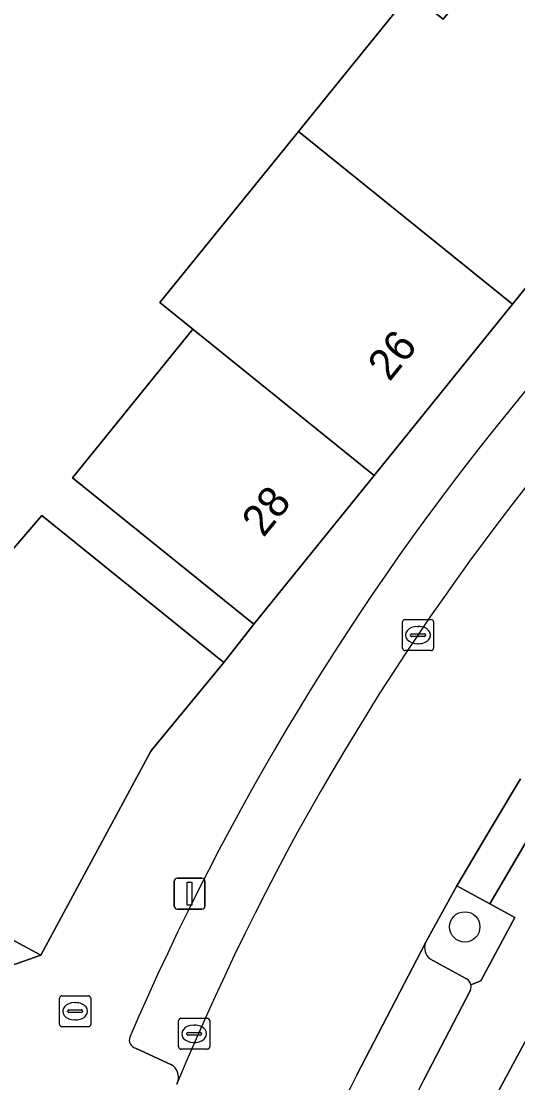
# Model space of a CAD drawing. Extents: x 159716 to 160783, y 383290 to 384031.
# Drawn here: x 160307.9 to 160323.91, y 383399.58 to 383433.83 of the extents above; entities that cross this region are included whole.
import ezdxf

# ---------------------------------------------------------------- set-up
doc = ezdxf.new("R2010")
doc.units = 0
for name, color, linetype in [('IMGEO_Boom', 7, 'Continuous'), ('IMGEO_Brandkraan', 7, 'Continuous'), ('IMGEO_Erf', 7, 'Continuous'), ('IMGEO_Groenvoorziening', 7, 'Continuous'), ('IMGEO_Kolk', 7, 'Continuous'), ('IMGEO_Lichtmast', 7, 'Continuous'), ('IMGEO_Pand', 7, 'Continuous'), ('IMGEO_Pand_nummerreeks', 7, 'Continuous'), ('IMGEO_Parkeervlak_open', 7, 'Continuous'), ('IMGEO_Rijbaan_lokaal_open', 7, 'Continuous'), ('IMGEO_Voetpad_open', 7, 'Continuous')]:
    doc.layers.add(name, color=color, linetype=linetype)

msp = doc.modelspace()

# ---------------------------------------------------------------- linework, layer by layer
at = {"layer": 'IMGEO_Boom'}
msp.add_circle((160322.206, 383404.609), 0.489, dxfattribs=at)
at = {"layer": 'IMGEO_Brandkraan'}
for p, q in [((160309.139, 383401.46), (160309.139, 383402.312)), ((160309.214, 383402.386), (160310.066, 383402.386)), ((160310.14, 383402.312), (160310.14, 383401.46)), ((160309.441, 383401.929), (160309.839, 383401.929)), ((160309.627, 383402.166), (160309.652, 383402.166)), ((160309.398, 383401.88), (160309.398, 383401.892)), ((160309.836, 383401.843), (160309.438, 383401.843)), ((160309.65, 383401.606), (160309.625, 383401.606)), ((160309.882, 383401.892), (160309.882, 383401.88)), ((160310.066, 383401.386), (160309.214, 383401.386))]:
    msp.add_line(p, q, dxfattribs=at)
for points in [[(160309.139, 383401.46), (160309.139, 383402.312)], [(160309.214, 383402.386), (160310.066, 383402.386)], [(160310.14, 383402.312), (160310.14, 383401.46)], [(160310.066, 383401.386), (160309.214, 383401.386)]]:
    msp.add_lwpolyline(points, dxfattribs=at)
for centre, radius, start, end in [((160309.216, 383402.31), 0.0765, 91.552, 178.448), ((160309.216, 383402.31), 0.0765, 91.552, 178.448), ((160310.064, 383402.31), 0.0765, 1.552, 88.448), ((160310.064, 383402.31), 0.0765, 1.552, 88.448), ((160309.438, 383401.889), 0.0403, 85.8775, 175.7526), ((160309.843, 383401.891), 0.0386, 1.7309, 96.639), ((160309.435, 383401.879), 0.0366, 178.938, 274.7102), ((160309.839, 383401.886), 0.043, 264.8664, 352.4533), ((160309.216, 383401.462), 0.0765, 181.552, 268.448), ((160309.216, 383401.462), 0.0765, 181.552, 268.448), ((160310.064, 383401.462), 0.0765, 271.552, 358.448), ((160310.064, 383401.462), 0.0765, 271.552, 358.448)]:
    msp.add_arc(centre, radius, start, end, dxfattribs=at)
for centre, major_axis, ratio, start_param, end_param in [((160309.626, 383401.886), (-0.387, 0.002), 0.722429, 4.712389, 7.853982), ((160309.651, 383401.886), (-0.39, 0.002), 0.717154, 1.570796, 4.712389)]:
    msp.add_ellipse(centre, major_axis=major_axis, ratio=ratio, start_param=start_param, end_param=end_param, dxfattribs=at)
at = {"layer": 'IMGEO_Erf'}
msp.add_lwpolyline([(160305.278, 383414.052), (160308.565, 383417.879), (160314.432, 383413.138), (160315.404, 383414.378), (160309.554, 383419.103), (160313.43, 383423.901), (160312.375, 383424.754), (160316.84, 383430.281), (160320.453, 383434.753), (160321.507, 383433.901), (160326.319, 383439.857), (160327.363, 383439.013), (160330.852, 383443.362), (160330.036, 383444.593), (160325.09, 383452.053), (160320.906, 383458.365), (160327.156, 383462.508)], dxfattribs=at)
at = {"layer": 'IMGEO_Groenvoorziening'}
for points in [[(160323.018, 383405.349), (160321.949, 383405.931), (160320.969, 383404.161), (160320.94, 383404.099)], [(160322.402, 383402.741), (160322.724, 383402.864), (160323.82, 383404.913), (160323.018, 383405.349)], [(160321.083, 383403.578), (160322.258, 383402.931)]]:
    msp.add_lwpolyline(points, dxfattribs=at)
for centre, radius, start, end in [((160321.364, 383403.935), 0.454, 158.8551, 231.8411), ((160322.127, 383402.682), 0.282, 12.1167, 62.1999)]:
    msp.add_arc(centre, radius, start, end, dxfattribs=at)
at = {"layer": 'IMGEO_Kolk'}
for p, q in [((160320.196, 383413.6), (160320.196, 383414.452)), ((160320.271, 383414.526), (160321.123, 383414.526)), ((160320.684, 383414.306), (160320.709, 383414.306)), ((160321.197, 383414.452), (160321.197, 383413.6)), ((160320.455, 383414.02), (160320.455, 383414.032)), ((160320.893, 383413.983), (160320.495, 383413.983)), ((160320.498, 383414.069), (160320.896, 383414.069)), ((160320.939, 383414.032), (160320.939, 383414.02)), ((160320.707, 383413.746), (160320.682, 383413.746)), ((160321.123, 383413.526), (160320.271, 383413.526)), ((160312.977, 383400.734), (160312.977, 383401.586)), ((160313.052, 383401.66), (160313.904, 383401.66)), ((160313.978, 383401.586), (160313.978, 383400.734)), ((160313.465, 383401.44), (160313.49, 383401.44)), ((160313.236, 383401.154), (160313.236, 383401.166)), ((160313.674, 383401.117), (160313.276, 383401.117)), ((160313.279, 383401.203), (160313.677, 383401.203)), ((160313.72, 383401.166), (160313.72, 383401.154)), ((160313.904, 383400.66), (160313.052, 383400.66)), ((160313.488, 383400.88), (160313.463, 383400.88))]:
    msp.add_line(p, q, dxfattribs=at)
for points in [[(160320.196, 383413.6), (160320.196, 383414.452)], [(160320.271, 383414.526), (160321.123, 383414.526)], [(160321.197, 383414.452), (160321.197, 383413.6)], [(160321.123, 383413.526), (160320.271, 383413.526)], [(160312.977, 383400.734), (160312.977, 383401.586)], [(160313.052, 383401.66), (160313.904, 383401.66)], [(160313.978, 383401.586), (160313.978, 383400.734)], [(160313.904, 383400.66), (160313.052, 383400.66)]]:
    msp.add_lwpolyline(points, dxfattribs=at)
for centre, radius, start, end in [((160320.273, 383414.45), 0.0765, 91.552, 178.448), ((160320.273, 383414.45), 0.0765, 91.552, 178.448), ((160321.121, 383414.45), 0.0765, 1.552, 88.448), ((160321.121, 383414.45), 0.0765, 1.552, 88.448), ((160320.495, 383414.029), 0.0403, 85.8775, 175.7526), ((160320.492, 383414.019), 0.0366, 178.938, 274.7102), ((160320.896, 383414.026), 0.043, 264.8664, 352.4533), ((160320.9, 383414.031), 0.0386, 1.7309, 96.639), ((160320.273, 383413.602), 0.0765, 181.552, 268.448), ((160320.273, 383413.602), 0.0765, 181.552, 268.448), ((160321.121, 383413.602), 0.0765, 271.552, 358.448), ((160321.121, 383413.602), 0.0765, 271.552, 358.448), ((160313.054, 383401.584), 0.0765, 91.552, 178.448), ((160313.054, 383401.584), 0.0765, 91.552, 178.448), ((160313.902, 383401.584), 0.0765, 1.552, 88.448), ((160313.902, 383401.584), 0.0765, 1.552, 88.448), ((160313.276, 383401.163), 0.0403, 85.8775, 175.7526), ((160313.273, 383401.153), 0.0366, 178.938, 274.7102), ((160313.677, 383401.16), 0.043, 264.8664, 352.4533), ((160313.681, 383401.165), 0.0386, 1.7309, 96.639), ((160313.054, 383400.736), 0.0765, 181.552, 268.448), ((160313.054, 383400.736), 0.0765, 181.552, 268.448), ((160313.902, 383400.736), 0.0765, 271.552, 358.448), ((160313.902, 383400.736), 0.0765, 271.552, 358.448)]:
    msp.add_arc(centre, radius, start, end, dxfattribs=at)
for centre, major_axis, ratio, start_param, end_param in [((160320.683, 383414.026), (-0.387, 0.002), 0.722429, 4.712389, 7.853982), ((160320.708, 383414.026), (-0.39, 0.002), 0.717154, 1.570796, 4.712389), ((160313.464, 383401.16), (-0.387, 0.002), 0.722429, 4.712389, 7.853982), ((160313.489, 383401.16), (-0.39, 0.002), 0.717154, 1.570796, 4.712389)]:
    msp.add_ellipse(centre, major_axis=major_axis, ratio=ratio, start_param=start_param, end_param=end_param, dxfattribs=at)
at = {"layer": 'IMGEO_Lichtmast'}
for p, q in [((160312.835, 383405.281), (160312.835, 383406.081)), ((160312.835, 383406.081), (160312.835, 383405.281)), ((160312.935, 383406.181), (160313.725, 383406.181)), ((160313.725, 383406.181), (160312.935, 383406.181)), ((160313.825, 383406.081), (160313.825, 383405.281)), ((160313.825, 383405.281), (160313.825, 383406.081)), ((160313.725, 383405.181), (160312.935, 383405.181)), ((160312.935, 383405.181), (160313.725, 383405.181))]:
    msp.add_line(p, q, dxfattribs=at)
msp.add_lwpolyline([(160313.255, 383406.056), (160313.405, 383406.056), (160313.405, 383405.306), (160313.255, 383405.306), (160313.255, 383406.056)], dxfattribs=at)
for centre, start, end in [((160312.935, 383406.081), 90, 180), ((160312.935, 383406.081), 90, 180), ((160313.725, 383406.081), 0, 90), ((160313.725, 383406.081), 360, 90), ((160312.935, 383405.281), 180, 270), ((160312.935, 383405.281), 180, 270), ((160313.725, 383405.281), 270, 0), ((160313.725, 383405.281), 270, 0)]:
    msp.add_arc(centre, 0.1, start, end, dxfattribs=at)
at = {"layer": 'IMGEO_Pand'}
for points in [[(160327.363, 383439.013), (160326.319, 383439.857), (160321.507, 383433.901), (160320.453, 383434.753), (160316.84, 383430.281), (160323.745, 383424.702), (160327.357, 383429.173), (160332.168, 383435.128)], [(160316.84, 383430.281), (160312.375, 383424.754), (160313.43, 383423.901), (160319.278, 383419.173), (160323.745, 383424.702)], [(160319.278, 383419.173), (160313.43, 383423.901), (160309.554, 383419.103), (160315.404, 383414.378)], [(160314.432, 383413.138), (160308.565, 383417.879), (160305.278, 383414.052), (160301.229, 383416.233), (160301.703, 383417.114), (160297.354, 383419.456), (160296.963, 383418.731), (160294.569, 383422.297), (160293.05, 383421.278), (160288.325, 383418.106), (160292.027, 383412.59), (160308.536, 383403.698), (160312.071, 383410.253), (160312.111, 383410.327)], [(160337.597, 383398.179), (160338.095, 383399.139), (160327.755, 383406.719), (160327.556, 383406.448), (160327.951, 383406.158), (160326.397, 383404.048), (160325.966, 383404.28), (160323.097, 383398.955), (160324.502, 383398.272), (160324.727, 383398.163), (160336.183, 383391.701), (160340.737, 383389.144), (160342.776, 383393.075)]]:
    msp.add_lwpolyline(points, close=True, dxfattribs=at)
at = {"layer": 'IMGEO_Parkeervlak_open'}
for points in [[(160320.94, 383404.099), (160318.723, 383399.836)], [(160322.258, 383402.931), (160321.083, 383403.578)], [(160320.88, 383399.672), (160322.386, 383402.565)], [(160311.584, 383400.698), (160312.748, 383400.159)]]:
    msp.add_lwpolyline(points, dxfattribs=at)
for centre, radius, start, end in [((160390.107, 383367.247), 85.657, 125.06609, 156.75807), ((160388.741, 383368.207), 82.037, 124.26536, 157.48827), ((160321.364, 383403.935), 0.454, 158.8551, 231.8411), ((160322.127, 383402.682), 0.282, 12.1167, 62.1999), ((160322.124, 383402.678), 0.285, 336.7577, 12.8535), ((160311.659, 383400.96), 0.273, 160.9671, 254.105), ((160312.507, 383399.756), 0.469, 342.7403, 59.0653), ((160400.482, 383358.736), 91.508, 153.31144, 161.91012), ((160410.195, 383354.715), 99.991, 153.28158, 161.04988)]:
    msp.add_arc(centre, radius, start, end, dxfattribs=at)
at = {"layer": 'IMGEO_Rijbaan_lokaal_open'}
for points in [[(160318.723, 383399.836), (160320.94, 383404.099), (160320.969, 383404.161), (160321.949, 383405.931), (160323.124, 383407.913), (160324.007, 383409.389)], [(160312.955, 383399.617), (160312.922, 383399.536)]]:
    msp.add_lwpolyline(points, dxfattribs=at)
for centre, radius, start, end in [((160388.741, 383368.207), 82.037, 124.26536, 157.48827), ((160400.482, 383358.736), 91.508, 153.31144, 161.91012)]:
    msp.add_arc(centre, radius, start, end, dxfattribs=at)
at = {"layer": 'IMGEO_Voetpad_open'}
for points in [[(160300.31, 383404.798), (160305.136, 383402.498), (160308.536, 383403.698), (160292.027, 383412.59), (160288.325, 383418.106), (160293.05, 383421.278), (160291.649, 383423.394), (160286.967, 383420.378), (160280.753, 383416.123), (160274.909, 383424.987), (160270.745, 383431.284), (160270.765, 383431.297), (160270.679, 383431.426), (160270.66, 383431.413), (160266.714, 383437.398), (160264.378, 383440.941), (160263.158, 383442.791), (160263.2, 383442.818), (160263.145, 383442.902), (160263.107, 383442.877), (160259.139, 383448.864)], [(160345.705, 383442.373), (160344.54, 383442.016), (160340.82, 383441.834), (160333.896, 383437.267), (160332.168, 383435.128), (160327.357, 383429.173), (160323.745, 383424.702), (160319.278, 383419.173), (160315.404, 383414.378), (160314.432, 383413.138), (160312.111, 383410.327), (160312.071, 383410.253), (160308.536, 383403.698), (160305.136, 383402.498), (160302.863, 383398.025)], [(160311.554, 383374.506), (160315.48, 383383.61), (160316.304, 383383.157), (160319.229, 383388.45), (160319.536, 383388.281), (160320.531, 383390.197), (160319.089, 383390.972), (160323.097, 383398.955), (160325.966, 383404.28), (160326.397, 383404.048), (160327.951, 383406.158), (160327.556, 383406.448), (160327.755, 383406.719), (160336.495, 383418.61), (160336.818, 383418.367), (160344.251, 383427.204), (160344.049, 383427.352), (160344.764, 383427.86), (160347.581, 383428.877), (160367.001, 383435.99), (160376.083, 383439.317)], [(160324.007, 383409.389), (160323.124, 383407.913), (160321.949, 383405.931), (160323.018, 383405.349), (160324.157, 383407.299), (160325.242, 383409.113)], [(160325.696, 383408.846), (160325.242, 383409.113), (160324.157, 383407.299), (160323.018, 383405.349), (160323.82, 383404.913), (160322.724, 383402.864), (160322.402, 383402.741)], [(160322.386, 383402.565), (160320.88, 383399.672)], [(160312.748, 383400.159), (160311.584, 383400.698)], [(160312.922, 383399.536), (160312.955, 383399.617)]]:
    msp.add_lwpolyline(points, dxfattribs=at)
for centre, radius, start, end in [((160390.107, 383367.247), 85.657, 125.06609, 156.75807), ((160322.124, 383402.678), 0.285, 336.7577, 12.8535), ((160311.659, 383400.96), 0.273, 160.9671, 254.105), ((160312.507, 383399.756), 0.469, 342.7403, 59.0653), ((160410.195, 383354.715), 99.991, 153.28158, 161.04988)]:
    msp.add_arc(centre, radius, start, end, dxfattribs=at)

# ---------------------------------------------------------------- texts
at = {"layer": 'IMGEO_Pand_nummerreeks'}
for s, p in [('26', (160319.776, 383422.177)), ('28', (160315.713, 383417.149))]:
    msp.add_text(s, height=1, rotation=51.0677, dxfattribs=at).set_placement(p)

doc.saveas('drawing.dxf')
